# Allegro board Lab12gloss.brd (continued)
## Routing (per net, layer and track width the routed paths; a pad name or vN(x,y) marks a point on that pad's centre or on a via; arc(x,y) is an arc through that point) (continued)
MEMORY.RA14: length 158.4
  TOP w0.15: 91.75,95.47 v1(93.98,95.47) ; 91.75,95.47 91.75,95.81 89.98,97.59 77.89,97.59 77.67,97.37 73,97.37 72.84,97.52 70.76,97.52 70.06,96.83 67.05,96.83 66.66,96.44 66.66,95.54 67.28,94.92 U5.60 ; 91.75,95.47 U18.15 ; v1(115.99,92.59) 115.99,94.15 115.86,94.28 U22.15 ; U21.15 115.86,81.28 115.99,81.41 v1(115.99,82.97) ; U17.15 91.75,81.94 92.85,83.04 93.67,83.04 v1(94.24,82.47) ; v1(93.55,105.64) 92.73,105.64 91.75,106.61 U19.15 ; U23.15 115.25,108.97 v1(116.12,109.84) ; U16.15 91.75,69.55 93.01,70.8 v1(95.12,70.8) 101.51,70.8 102.02,70.29 102.02,69.44 101.92,69.34 101.92,67.28 104.43,64.77 113.86,64.77 115.25,66.17 U20.15 v1(115.25,69.9)
  BOTTOM w0.15: v1(116.12,109.84) 115.25,108.97 115.25,93.32 v1(115.99,92.59) v1(115.99,82.97) 115.99,70.63 v1(115.25,69.9) ; 94.98,82.47 94.98,91.15 95.01,91.19 95.01,94.43 v1(93.98,95.47) 93.98,105.2 v1(93.55,105.64) ; 94.98,82.47 95.12,82.32 v1(95.12,70.8) ; 94.98,82.47 v1(94.24,82.47)
MEMORY.RA15: length 176.2
  TOP w0.15: U23.14 113.98,106.02 114.36,105.64 v1(115.99,105.64) ; v1(89.52,76.1) 89.85,76.44 89.85,78.78 89.95,78.88 89.95,79.48 90.48,80.02 U17.14 ; U19.14 90.48,105.56 v1(90.26,105.34) ; v1(90.48,65.93) U16.14 v1(90.48,71.8) ; U5.58 v1(70.55,92.38) ; U22.14 113.98,95.97 115.17,97.16 v1(115.99,97.16) ; U18.14 v1(90.48,95.9) ; U20.14 113.98,67.62 113.19,66.82 113.19,66.38 v1(113.77,65.8) ; v1(117.45,83.71) 115.13,83.71 113.98,82.56 U21.14
  BOTTOM w0.15: v1(70.55,92.38) 70.93,92.01 70.93,72.15 77.15,65.93 v1(90.48,65.93) 90.61,65.8 v1(113.77,65.8) 117.45,69.49 v1(117.45,83.71) 117.45,96.53 116.82,97.16 v1(115.99,97.16) v1(115.99,105.64) ; v1(90.48,71.8) 90.48,76.1 ; 90.48,76.1 v1(89.52,76.1) ; 90.48,76.1 v1(90.48,95.9) 90.48,105.12 v1(90.26,105.34)
MEMORY.RCS0: length 39
  TOP w0.15: 79.59,74.84 80.68,73.75 80.68,70.84 80.33,70.49 U16.6 ; 79.59,74.84 79.59,76.56 79.69,76.66 79.69,79 80.33,79.64 U17.6 ; 79.59,74.84 79.29,74.54 73.96,74.54 72.69,75.81 72.69,82.52 72.3,82.92 65.4,82.92 64.16,84.16 U5.51
MEMORY.RCS1: length 47.7
  TOP w0.15: v1(80.33,105.41) U19.6 ; 79.79,94.17 79.79,93.12 79.69,93.22 79.69,95.8 v1(79.79,95.9) ; 79.79,94.17 80.21,94.17 U18.6 ; 79.79,94.17 79.79,93.33 79.55,93.09 77.29,93.09 77.15,93.23 77.15,96.14 76.53,96.77 73.78,96.77 v1(72.92,95.9) ; v1(62.89,95.9) U5.50
  BOTTOM w0.15: v1(72.92,95.9) v1(62.89,95.9) ; v1(80.33,105.41) 79.68,104.77 79.68,96 v1(79.79,95.9)
MEMORY.RCS2: length 70.2
  TOP w0.15: U21.6 v1(103.83,79.64) ; v1(71.96,82.18) 64.21,82.18 61.62,84.78 U5.49 ; U20.6 v1(103.83,69.9)
  BOTTOM w0.15: v1(103.83,79.64) 103.09,78.91 103.09,70.63 v1(103.83,69.9) 102.19,68.27 75.77,68.27 71.96,72.08 v1(71.96,82.18)
MEMORY.RCS3: length 73.9
  TOP w0.15: U22.6 v1(103.83,92.76) ; U23.6 v1(103.83,109.26) ; U5.48 v1(60.35,94.38)
  GND w0.15: v1(103.83,92.76) 103,91.93 73.43,91.93 70.97,94.38 v1(60.35,94.38)
  BOTTOM w0.15: v1(103.83,109.26) 103.83,104.02 103.25,103.45 103.25,93.33 v1(103.83,92.76)
MEMORY.RD0: length 153.7
  TOP w0.15: U5.81 v1(59.08,98.12) ; U20.7 v1(105.09,66.66) 105.83,65.93 108.16,65.93 109.54,67.31 109.54,69.39 111.84,71.69 115.77,71.69 118.19,74.11 118.19,84.13 115.65,86.67 107.39,86.67 105.61,88.45 105.61,89.53 105.73,89.64 105.73,92.13 105.09,92.77 U22.7 ; U16.7 v1(81.59,66.66) ; v1(73.78,92.66) 81.24,92.66 81.59,93.02 U18.7
  BOTTOM w0.15: v1(105.09,66.66) v1(81.59,66.66) 76.94,66.66 71.23,72.38 71.23,90.11 v1(73.78,92.66) 73.78,96.09 71.75,98.12 v1(59.08,98.12)
MEMORY.RD1: length 173.2
  TOP w0.15: 108.91,73.73 v1(116.72,73.73) ; 108.91,73.73 U20.10 ; 108.91,73.73 86.2,73.73 85.41,72.94 U16.10 85.41,67.02 84.02,65.63 81.35,65.63 79.69,67.29 79.69,71.31 77.41,73.6 73.95,73.6 66.42,81.12 64.26,81.12 60.98,84.4 60.98,87.13 61.08,87.23 61.08,94.76 59.05,96.79 v1(57.81,96.79) U5.82 ; U22.10 108.91,93.89 109.7,93.09 114.38,93.09 114.62,93.34 114.62,95.22 115.3,95.9 v1(116.72,95.9) ; v1(71.89,96.79) 72.7,96.79 72.97,97.06 78.27,97.06 78.49,97.29 84.26,97.29 85.41,96.15 U18.10
  BOTTOM w0.15: v1(71.89,96.79) v1(57.81,96.79) ; v1(116.72,73.73) v1(116.72,95.9)
MEMORY.RD2: length 137.9
  TOP w0.15: U16.23 85.41,75.35 86.42,74.34 107.25,74.34 108.91,75.99 U20.23 v1(108.91,79.34) ; U18.23 85.41,105.16 84.67,105.9 v1(84.67,109.99) 86.1,109.99 87.04,110.93 103.29,110.93 104.56,109.66 104.56,108.44 104.46,108.34 104.46,106.32 104.69,106.09 106.76,106.09 107,106.34 107,108.33 107.14,108.47 108.11,108.47 108.27,108.31 108.27,106.22 108.91,105.59 U22.23 v1(108.91,100.91) ; U5.83 v1(56.54,111.97)
  BOTTOM w0.15: v1(56.54,111.97) 60.73,116.16 77.07,116.16 77.85,115.38 77.85,115.37 79.42,113.8 79.42,111.87 80.56,110.72 83.94,110.72 v1(84.67,109.99) ; v1(108.91,100.91) 110.14,99.67 110.14,97.01 107.6,94.47 107.24,94.47 105.59,92.82 105.59,88.33 103.55,86.29 103.55,84.69 v1(108.91,79.34)
MEMORY.RD3: length 162.5
  TOP w0.15: v1(92.79,101.57) 92.19,100.97 82.74,100.97 81.59,102.11 U18.26 ; v1(105.31,105.34) 105.31,103.94 U22.26 ; U20.26 v1(105.09,76.1) 103.63,74.64 86.56,74.64 86.04,75.16 86.04,78.66 85.8,78.91 82.4,78.91 81.59,78.11 U16.26 ; v1(55.21,116.49) 54.63,115.92 54.63,115.86 55.27,115.22 U5.84
  BOTTOM w0.15: 92.49,115.59 92.79,115.29 v1(92.79,101.57) ; 92.49,115.59 87.41,115.59 85.87,114.04 80.02,114.04 78.45,115.62 78.45,115.63 77.32,116.76 56.28,116.76 56.02,116.49 v1(55.21,116.49) ; 92.49,115.59 92.49,115.89 104.07,115.89 104.56,115.4 104.56,113.84 103.55,112.83 103.55,111.17 105.31,109.41 v1(105.31,105.34) 107.08,103.57 109.64,103.57 110.91,102.3 110.91,79 109.64,77.73 106.73,77.73 v1(105.09,76.1)
MEMORY.RD4: length 133.7
  TOP w0.15: v1(94.28,111.97) 94.28,111.23 ; 94.28,111.23 86.91,111.23 86.65,110.97 81.63,110.97 81.59,110.93 ; 94.28,111.23 103.44,111.23 105.09,109.58 U23.7 ; 81.59,110.93 80.37,110.93 79.58,111.73 79.58,115.53 79.69,115.64 79.69,117.66 79.45,117.91 77.38,117.91 77.15,117.68 77.15,115.66 77.25,115.56 77.25,114.49 76.85,114.09 73.62,114.09 73.22,114.49 73.22,115.49 71.19,117.53 55.14,117.53 54,116.38 U5.1 ; 81.59,110.93 U19.7 ; U21.7 v1(105.09,79.66) ; v1(95.88,85.57) 86.56,85.57 86.04,85.05 86.04,80.34 85.8,80.09 82.4,80.09 81.59,80.89 U17.7
  VCC w0.15: v1(95.88,85.57) 99.19,85.57 v1(105.09,79.66)
  BOTTOM w0.15: v1(95.88,85.57) 95.28,86.17 95.28,89.95 95.31,89.99 95.31,96.88 94.28,97.91 v1(94.28,111.97)
MEMORY.RD5: length 146.8
  TOP w0.15: U19.10 85.41,108.74 v1(85.92,109.26) ; U5.2 52.73,117.47 51.94,118.26 51.31,118.26 49.55,116.51 49.55,112.89 51.94,110.51 v1(57.08,110.51) ; U17.10 85.41,84.91 86.93,86.43 v1(96.74,86.43) 105.28,86.43 105.34,86.37 108.86,86.37 108.91,86.32 U21.10 ; v1(96.74,112) 101.88,112 102.61,112.73 104.71,112.73 108.91,108.54 U23.10
  GND w0.15: v1(85.92,109.26) 88.48,109.26 94.66,115.44 95.34,115.44 96.74,114.04 v1(96.74,112)
  BOTTOM w0.15: v1(57.08,110.51) 62.43,115.86 76.94,115.86 77.55,115.25 77.55,115.24 79.12,113.67 79.12,111.69 80.52,110.29 83.1,110.29 84.14,109.26 v1(85.92,109.26) ; v1(96.74,86.43) 96.74,88.93 96.46,89.21 96.46,110.9 96.74,111.19 v1(96.74,112)
MEMORY.RD6: length 132.2
  TOP w0.15: v1(51.46,117.23) U5.3 ; U21.23 108.91,91.98 108.39,92.5 108.39,93.09 ; v1(111.94,96.5) 109.53,96.5 108.27,95.24 108.27,93.21 108.39,93.09 ; U23.23 v1(108.91,115.1) ; U17.23 85.41,91.11 86.2,91.91 99.22,91.91 99.38,91.75 99.38,89.38 101.13,87.64 103.54,87.64 104.56,88.65 104.56,89.56 104.46,89.66 104.46,91.78 104.56,91.88 104.56,93.12 104.46,93.22 104.46,95.24 104.69,95.47 106.84,95.47 107,95.31 107,93.32 107.22,93.09 108.39,93.09 ; v1(85.41,114.85) U19.23
  BOTTOM w0.15: v1(51.46,117.23) 83.03,117.23 v1(85.41,114.85) 87.15,116.59 107.42,116.59 v1(108.91,115.1) 110.29,115.1 111.94,113.45 v1(111.94,96.5)
MEMORY.RD7: length 121
  TOP w0.15: U5.4 50.19,113.28 50.81,112.66 52.98,112.66 53.36,113.05 53.36,116.19 55.68,118.5 81.08,118.5 81.59,117.98 U19.26 81.59,115.2 83.26,113.54 85.87,113.54 86.7,112.72 87.3,112.72 87.35,112.77 89.65,112.77 90.43,113.54 v1(96.01,113.54) 103.44,113.54 105.09,115.19 U23.26 ; U21.26 105.09,88.7 103.7,87.31 96.74,87.31 v1(96.01,88.04) 92.78,88.04 92.66,87.92 82.87,87.92 81.59,89.19 U17.26
  BOTTOM w0.15: v1(96.01,88.04) v1(96.01,113.54)
MEMORY.RWE: length 229.5
  TOP w0.15: U21.11 110.17,81.94 113.1,84.87 v1(115.25,84.87) ; v1(87.69,72.1) 86.67,71.08 U16.11 v1(86.67,65.19) ; U22.11 110.17,95.55 110.39,95.77 112.28,95.77 113.67,97.16 113.67,97.59 113.97,97.89 ; U5.56 v1(66.31,89.84) ; U20.11 110.17,68.94 111.89,70.66 v1(114.09,70.66) 115.19,70.66 118.49,73.96 118.49,95.73 116.33,97.89 113.97,97.89 ; 110.45,108.77 110.45,108.9 105.61,113.73 105.61,115.53 105.73,115.64 105.73,117.75 104.98,118.5 89.33,118.5 88.58,117.75 88.58,115.31 89.35,114.54 v1(89.35,113.5) ; 110.45,108.77 110.81,108.41 110.81,106.22 110.91,106.12 110.91,104.88 110.81,104.78 110.81,102.66 110.91,102.56 110.91,100.96 113.97,97.89 ; 110.45,108.77 110.17,108.49 U23.11 ; U18.11 86.67,95.75 87.55,96.63 v1(88.37,96.63) ; U17.11 v1(86.67,79.66) ; U19.11 86.67,106.39 87.43,105.64 v1(88.37,105.64)
  BOTTOM w0.15: v1(87.69,72.1) 87.69,78.31 ; 87.69,78.31 87.69,78.65 v1(86.67,79.66) ; 87.69,78.31 89.31,78.31 89.95,78.94 89.95,92.44 89.75,92.63 89.75,98.63 89.95,98.83 89.95,102.14 89.55,102.53 88.37,102.53 ; 88.37,102.53 v1(88.37,105.64) 89.35,106.62 v1(89.35,113.5) ; 88.37,102.53 v1(88.37,96.63) ; v1(115.25,84.87) 115.25,71.83 v1(114.09,70.66) ; v1(86.67,65.19) 84.16,62.68 71.1,62.68 69.2,64.59 69.2,86.95 v1(66.31,89.84)
MRD: length 49.6
  TOP w0.15: U2.9 51.38,65.94 51.38,63.86 46.75,59.23 46.75,56.12 43.48,52.85 42.12,52.85 42.03,52.95 13.45,52.95 12.87,53.52 J1.46
MWR: length 53.2
  TOP w0.15: J1.45 13.35,52.55 43.72,52.55 47.95,56.77 47.95,57.91 51.67,61.65 51.67,68.19 U2.10
N00036_DATA_DAAMP: length 33.8
  TOP w0.15: U8.8 v1(84.85,42.67) ; U10.5 v1(94.48,41.09) ; U8.5 v1(84.85,38.86) v1(93.88,38.86)
  BOTTOM w0.15: L4.2 93.88,31.5 93.88,35.5 ; v1(84.85,42.67) v1(84.85,38.86) ; 93.88,35.5 93.88,38 ; 93.88,35.5 R7.1 ; v1(94.48,41.09) 93.88,40.5 v1(93.88,38.86) 93.88,38 ; 93.88,38 R6.1
N00036_DATA_DAAMP1: length 38.6
  TOP w0.15: U13.5 92.47,19.32 v1(93.71,18.08) ; L6.2 96.28,11.97 96.28,15.72 95.39,16.61 v1(93.69,16.61) 90.18,16.61 87.84,18.94 U11.5 81.84,18.94 79.94,20.85 79.94,21.61 81.08,22.75 U11.8
  BOTTOM w0.15: R9.1 93.47,15.58 93.69,15.8 v1(93.69,16.61) 93.69,18.06 v1(93.71,18.08) R8.1
N00038_DATA_DAAMP: length 23.2
  TOP w0.15: v1(80.32,37.59) U8.4 90.28,37.59 L3.2
  BOTTOM w0.15: C8.1 78.5,41.86 78.51,41.88 79.68,41.88 80.32,41.24 v1(80.32,37.59)
N00038_DATA_DAAMP1: length 22.3
  TOP w0.15: L5.2 90.71,13.08 86.11,17.67 U11.4 81.8,17.67 78.5,20.98 v1(78.5,22.3)
  BOTTOM w0.15: C11.1 v1(78.5,22.3)
N00044_DATA_DAAMP: length 12.7
  TOP w0.15: U9.2 95.7,39.93 95.43,40.2 91.65,40.2 91.02,40.84 91.02,41.66 90.2,42.48 90.2,43.76 89.06,44.91 U10.1
N00044_DATA_DAAMP1: length 11.5
  TOP w0.15: U13.1 v1(90.03,24.98)
  BOTTOM w0.15: 96.93,20.01 95.01,20.01 v1(90.03,24.98)
N00060_DATA_DAAMP: length 17.5
  TOP w0.15: U9.3 97.55,37.63 97.19,37.63 94.92,39.91 84.72,39.91 84.5,40.14 U8.6
N00060_DATA_DAAMP1: length 17.8
  TOP w0.15: U11.6 84.72,20.21 85.38,19.54 89.61,19.54 91.81,17.35 97.19,17.35 U12.3
N282866_DATA_DAAMP: length 11.2
  TOP w0.15: v1(91.23,45.86) 92.12,45.86 92.47,45.51 U10.8
  BOTTOM w0.15: v1(91.23,45.86) 91.23,43.97 88.83,41.56 88.83,38.62 89.44,38 R6.2
N282866_DATA_DAAMP1: length 10.3
  TOP w0.15: v1(90.83,19.79) 90.83,24.63 91.19,24.98 U13.8
  BOTTOM w0.15: v1(90.83,19.79) 89.59,19.79 88.83,19.02 88.83,18.7 89.44,18.08 R8.2
N282912_DATA_DAAMP: length 11.1
  TOP w0.15: U10.2 v1(89.17,43.63)
  BOTTOM w0.15: R7.2 89.28,35.5 88.53,36.25 88.53,42.99 v1(89.17,43.63)
N282912_DATA_DAAMP1: length 11.6
  TOP w0.15: U13.2 v1(89.53,23.71)
  BOTTOM w0.15: R9.2 89.28,15.58 88.53,16.33 88.53,22.71 v1(89.53,23.71)
NCS: length 19.2
  TOP w0.15: U5.11 41.3,108.66 40.89,108.25 30.86,108.25 30,107.39 U7.4
OE: length 21.3
  TOP w0.15: U5.32 38.16,87.3 35.89,89.57 35.89,98.13 30.94,103.08 U7.3
OUTA: length 15.6
  BOTTOM w0.15: U9.6 102.28,44.07 103.07,43.27 103.07,39.87 98.7,35.5 L1.1
OUTB: length 15.6
  BOTTOM w0.15: U12.6 102.3,24.14 103.07,23.37 103.07,20.03 98.62,15.58 L2.1
Q0: length 7
  TOP w0.15: R1.1 77.78,61 77.6,61.17 U6.18
Q1: length 6.9
  TOP w0.15: U6.16 77.72,58.63 77.86,58.5 R2.1
Q2: length 6.9
  TOP w0.15: U6.14 77.77,56.09 77.86,56 R3.1
Q3: length 6.9
  TOP w0.15: U6.12 77.81,53.55 77.86,53.5 R4.1
RDY: length 46.6
  TOP w0.15: U2.23 42.05,49.86 11.41,49.86 10.47,50.8 10.47,62.37 J1.50
RESET: length 73.1
  TOP w0.15: U5.15 20.39,108.89 v1(19,107.5)
  BOTTOM w0.15: v1(19,107.5) 9.71,107.5 3.5,101.29 3.5,80.62 6.73,77.39 7.19,77.39 10.11,74.47 10.11,72.97 J1.53
SEL: length 56.7
  TOP w0.15: v1(44.38,106.35) 44.38,115.51 44.13,115.76 38.78,115.76 37.51,114.49 37.51,112.06 38.14,111.43 U5.13
  BOTTOM w0.15: v1(44.38,106.35) 44.38,73.41 U2.14
V+12: length 213.2
  TOP w0.2: U13.4 86.23,21.17 86.04,21.37 86.04,25.55 88.71,28.22 v1(93.11,28.22) ; J1.64 J1.63 20.78,96.7 24.21,93.27 24.21,80.47 28.91,75.77 54.28,75.77 66,64.06 66,54.84 70.82,50.02 v1(92.44,50.02) ; U10.4 v1(90.03,41.09)
  BOTTOM w0.2: 92.74,45.49 99,45.49 ; 92.74,45.49 92.44,45.79 v1(92.44,50.02) ; 92.74,45.49 92.74,43.8 v1(90.03,41.09) ; 99,45.49 U9.7 ; 99,45.49 101.71,45.49 103.87,43.33 103.87,34.89 103.23,34.25 101.89,34.25 101.25,33.61 101.25,28.52 ; 101.25,28.52 103.87,25.9 103.87,19.92 98.28,14.33 94.26,14.33 93.01,13.08 C12.1 ; 101.25,28.52 99.3,28.52 99,28.22 ; 99,28.22 v1(93.11,28.22) 93.11,32.75 92.86,33 C9.1 ; 99,28.22 U12.7
VCLKA: length 82.1
  TOP w0.15: v1(68.2,78.23) 48.5,78.23 42.57,84.16 U5.34 ; U14.11 68.44,33.78 67.82,34.4 67.82,44.27 68.14,44.58 71.3,44.58 v1(71.94,45.22) U8.11
  BOTTOM w0.15: v1(71.94,45.22) 68.2,48.95 v1(68.2,78.23)
VCLKC: length 100.2
  TOP w0.15: U15.11 67.91,13.86 67.86,13.91 67.86,25.85 v1(68.34,26.33) 71.45,26.33 72.48,25.29 U11.11
  BOTTOM w0.15: R5.2 61.99,91.5 65.42,88.07 65.42,29.25 v1(68.34,26.33)
VD0: length 89.4
  TOP w0.15: U14.2 54.92,43.95 54.62,44.24 ; 53.83,28.5 53.83,28.09 57.89,24.02 U15.2 ; 53.83,28.5 v1(52.57,28.5) ; 53.83,28.5 53.83,43.45 54.62,44.24 ; 54.62,44.24 v1(54.62,58.66) 54.62,60.16 56.91,62.45 U6.2 ; U5.39 v1(48.92,83.81)
  BOTTOM w0.15: v1(48.92,83.81) 48.92,59.47 50.46,57.93 53.89,57.93 v1(54.62,58.66) ; R13.2 v1(52.57,28.5)
VD1: length 84.4
  TOP w0.15: U6.3 v1(56.69,61.17) ; U5.40 50.19,82.71 53.11,79.79 v1(55.22,79.79) ; v1(52.61,26) 55.85,22.75 U15.3 ; U14.3 v1(56.69,42.67)
  BOTTOM w0.15: R17.2 v1(52.61,26) 53.34,26.73 53.34,40.14 55.87,42.67 v1(56.69,42.67) v1(56.69,61.17) 55.22,62.64 v1(55.22,79.79)
VD2: length 95.2
  TOP w0.15: U6.4 v1(55.65,59.91) 55.65,47.72 v1(57.42,45.95) 61.93,45.95 62.56,45.31 62.56,42.79 61.17,41.41 U14.4 ; v1(53.78,21.73) 57.06,21.73 57.31,21.48 U15.4 ; U5.41 v1(51.46,83.81)
  BOTTOM w0.15: v1(55.65,59.91) 51.46,64.1 v1(51.46,83.81) ; v1(57.42,45.95) 57.42,42.36 56.53,41.47 55.18,41.47 53.78,40.07 53.78,23.5 ; 53.78,23.5 v1(53.78,21.73) ; 53.78,23.5 R12.2
VD3: length 88.6
  TOP w0.15: U6.5 v1(57.42,58.63) ; v1(54.95,21) 55.74,20.21 U15.5 ; U5.42 v1(52.73,81.25) ; U14.5 v1(54.95,40.14)
  BOTTOM w0.15: R16.2 v1(54.95,21) v1(54.95,40.14) 55.74,40.14 58.15,42.55 58.15,51.42 57.42,52.15 v1(57.42,58.63) 57.42,78.72 54.88,81.25 v1(52.73,81.25)
VD4: length 85.3
  TOP w0.15: U6.6 v1(58.45,57.37) ; v1(57.25,38.96) 57.34,38.86 U14.6 ; U15.6 v1(55.83,18.94) ; U5.43 v1(54,81.99)
  BOTTOM w0.15: R11.2 55.38,18.5 v1(55.83,18.94) 55.83,37.53 v1(57.25,38.96) 58.45,40.16 v1(58.45,57.37) 58.45,78.31 54.77,81.99 v1(54,81.99)
VD5: length 92.6
  TOP w0.15: U5.44 v1(55.27,83.01) ; U14.7 61.17,37.59 62.26,36.51 62.26,33.4 60.99,32.13 v1(58.88,32.13) ; U15.7 v1(56.95,17.67) ; U6.7 v1(59.92,56.09)
  BOTTOM w0.15: v1(55.27,83.01) 59.92,78.36 v1(59.92,56.09) 59.92,33.16 v1(58.88,32.13) 56.95,30.2 v1(56.95,17.67) 55.28,16 R15.2
VD6: length 95.6
  TOP w0.15: v1(62.26,79.79) 60.6,79.79 56.54,83.85 U5.45 ; U14.8 59.12,36.33 58.51,36.94 58.51,37.92 58.91,38.33 v1(62.26,38.33) 63.3,37.3 63.3,18.52 61.17,16.4 U15.8 58.31,16.4 v1(55.41,13.5) ; v1(64.39,54.83) U6.8
  BOTTOM w0.15: v1(62.26,38.33) 62.26,54.83 ; 62.26,54.83 v1(62.26,79.79) ; 62.26,54.83 v1(64.39,54.83) ; R10.2 v1(55.41,13.5)
VD7: length 87.8
  TOP w0.15: U6.9 v1(60.65,53.55) ; U14.9 v1(61.53,35.05) ; U5.46 v1(57.81,83.74) ; U15.9 v1(58.15,15.13)
  BOTTOM w0.15: 60.65,35.05 v1(61.53,35.05) ; 60.65,35.05 v1(60.65,53.55) 61.38,54.29 61.38,80.16 v1(57.81,83.74) ; 60.65,35.05 60.65,17.63 v1(58.15,15.13) 54.02,11 R14.2
VREF: length 26.3
  TOP w0.15: L5.1 102.5,12.25 104.75,10 R18.1
  BOTTOM w0.15: L5.1 104.44,15.02 104.44,31.05 L3.1
WAIT: length 44
  TOP w0.15: v1(39.07,83.81) 39.65,83.23 39.76,83.23 41.3,84.78 U5.33
  GND w0.15: J1.51 10.77,67.23 10.77,71.72 11.66,72.61 29.07,72.61 39.07,82.61 v1(39.07,83.81)
WSTAT: length 41.8
  TOP w0.15: v1(70.19,64.68) 70.19,53.03 70.94,52.28 U6.11 ; U5.57 v1(70.19,91.11)
  BOTTOM w0.15: v1(70.19,91.11) v1(70.19,64.68)
N14843: length 3.2
  BOTTOM w0.15: R16.1 C19.1
N14849: length 3.2
  BOTTOM w0.15: R12.1 C15.1
N14853: length 3.2
  BOTTOM w0.15: R17.1 C20.1
N14855: length 3.2
  BOTTOM w0.15: R13.1 C16.1
N15143: length 3.2
  BOTTOM w0.15: R14.1 C17.1
N15151: length 3.2
  BOTTOM w0.15: R10.1 C13.1
N15155: length 3.2
  BOTTOM w0.15: R15.1 C18.1
N15161: length 3.2
  BOTTOM w0.15: R11.1 C14.1
N58063: length 4.7
  TOP w0.15: U8.12 U14.19
N58118: length 4.7
  TOP w0.15: U8.13 U14.18
N58173: length 4.7
  TOP w0.15: U8.14 U14.17
N58228: length 4.7
  TOP w0.15: U8.15 U14.16
N58283: length 4.7
  TOP w0.15: U8.16 U14.15
N58338: length 4.7
  TOP w0.15: U8.17 U14.14
N58393: length 4.7
  TOP w0.15: U8.18 U14.13
N58448: length 4.7
  TOP w0.15: U8.19 U14.12
N58834: length 4.7
  TOP w0.15: U11.12 U15.19
N58889: length 4.7
  TOP w0.15: U11.13 U15.18
N58944: length 4.7
  TOP w0.15: U11.14 U15.17
N58999: length 4.7
  TOP w0.15: U11.15 U15.16
N59054: length 4.7
  TOP w0.15: U11.16 U15.15
N59109: length 4.7
  TOP w0.15: U11.17 U15.14
N59164: length 4.7
  TOP w0.15: U11.18 U15.13
N59219: length 4.7
  TOP w0.15: U11.19 U15.12
N409523: length 6.9
  TOP w0.15: U5.37 v1(46.38,91.5)
  BOTTOM w0.15: R5.1 v1(46.38,91.5)

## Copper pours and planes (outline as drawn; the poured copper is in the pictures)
GND on GND: 1,11.41 1,108.59 1.41,109 21,109 21,118.59 21.41,119 118.59,119 119,118.59 119,1.41 118.59,1 21.41,1 21,1.41 21,11 1.41,11 ; 2 cut-outs
VCC on VCC: 1,11.41 1,108.59 1.41,109 21,109 21,118.59 21.41,119 118.59,119 119,118.59 119,1.41 118.59,1 21.41,1 21,1.41 21,11 1.41,11 ; 2 cut-outs
